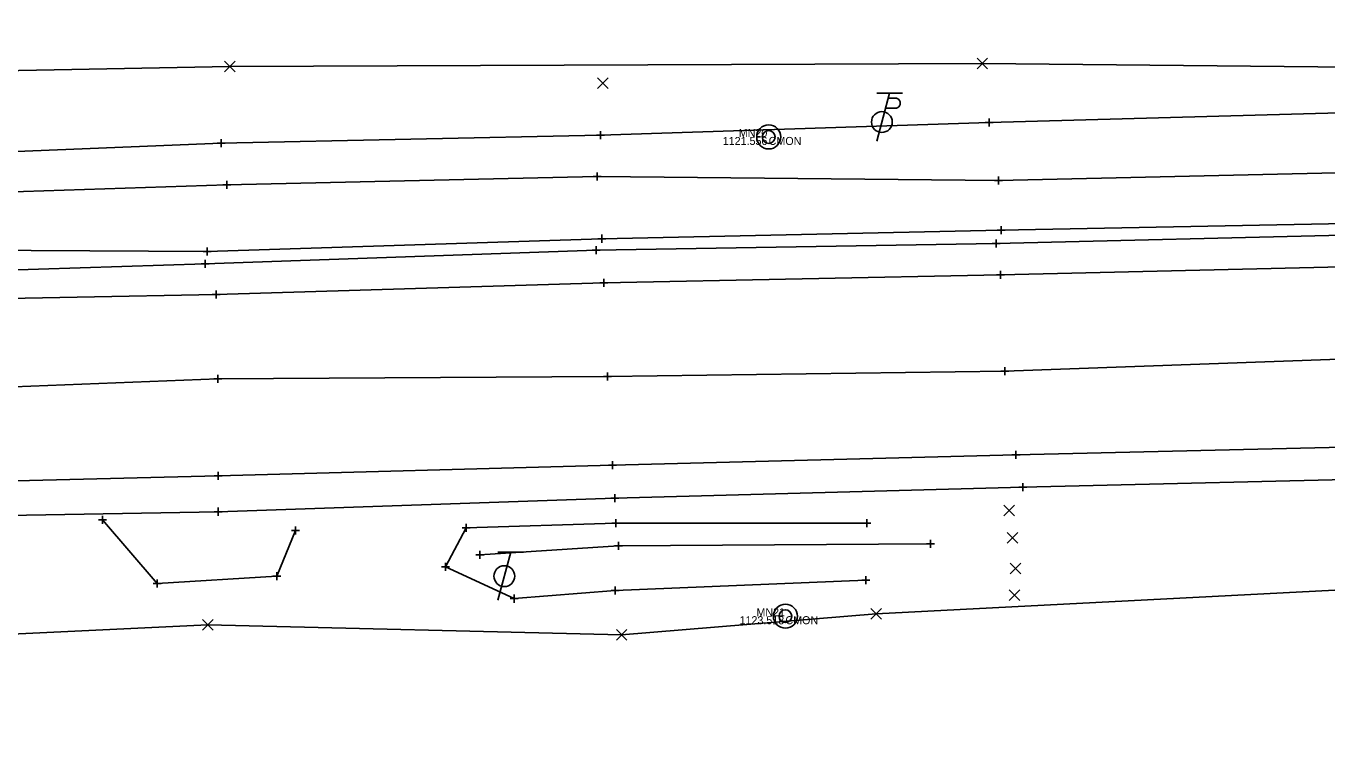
# Model space of a CAD drawing. Extents: x 2402028 to 2407435, y 498611 to 499105.
# Drawn here: x 2403515.5 to 2403678, y 498636.3 to 498725.5 of the extents above; entities that cross this region are included whole.
import ezdxf

# ---------------------------------------------------------------- set-up
doc = ezdxf.new("R2010")
doc.units = 0
for name, color, linetype in [('_CIVIL_CONSTRUCTION', 7, 'Continuous'), ('DR_X_Ditch', 7, 'Continuous'), ('PV_X_COP', 7, 'Continuous'), ('PV_X_Driveway', 7, 'Continuous'), ('PV_X_EOP', 7, 'Continuous'), ('PV_X_Shoulder', 7, 'Continuous'), ('RW_X_CL_1000_Distances', 7, 'Continuous'), ('RW_X_CL_100_Bearings', 7, 'Continuous'), ('RW_X_CL_100_Cardinal_Points', 7, 'Continuous'), ('RW_X_CL_100_Stations', 7, 'Continuous'), ('RW_X_CL_500_Bearings', 7, 'Continuous'), ('RW_X_CL_500_Cardinal_Points', 7, 'Continuous'), ('RW_X_CL_500_Stations', 7, 'Continuous'), ('SV_X_Break_Lines', 7, 'Continuous'), ('SV_X_Terrain_Boundary', 7, 'Continuous')]:
    doc.layers.add(name, color=color, linetype=linetype)

msp = doc.modelspace()

# ---------------------------------------------------------------- linework, layer by layer
at = {"layer": 'DR_X_Ditch'}
for points in [[(2403115.12, 498695.09), (2403139.28, 498697.03), (2403188.69, 498698.47), (2403237.26, 498698.52), (2403287.58, 498700.04), (2403338.31, 498701.02), (2403388.05, 498703.88), (2403439.2, 498702.19), (2403487.16, 498703.92), (2403540.55, 498705.7), (2403586.78, 498706.71), (2403636.91, 498706.23), (2403686.46, 498707.34), (2403736.22, 498708.05), (2403785.8, 498709.01), (2403836.25, 498710.7), (2403885.81, 498712.33), (2403935.71, 498713.55), (2403984.74, 498715.92), (2404035.79, 498716.24), (2404057.73, 498716.67)], [(2403628.45, 498660.85), (2403589.45, 498660.61), (2403572.15, 498659.5)]]:
    msp.add_lwpolyline(points, dxfattribs=at)
at = {"layer": 'PV_X_COP'}
msp.add_lwpolyline([(2403339.4, 498675.07), (2403388.6, 498676.54), (2403439.52, 498678.71), (2403488.39, 498679.45), (2403539.43, 498681.45), (2403588.1, 498681.77), (2403637.7, 498682.43), (2403687.6, 498684.21), (2403737.23, 498685.84), (2403787.81, 498686.93), (2403836.99, 498688.45), (2403886.41, 498689.66), (2403936.62, 498690.72), (2403985.57, 498692.23), (2404036.54, 498693.02)], dxfattribs=at)
at = {"layer": 'PV_X_Driveway'}
msp.add_lwpolyline([(2403549.12, 498662.52), (2403546.79, 498656.83), (2403531.83, 498655.92), (2403525, 498663.87)], dxfattribs=at)
at = {"layer": 'PV_X_EOP'}
for points in [[(2403338.61, 498686.54), (2403387.34, 498688.53), (2403437.74, 498689.31), (2403487.06, 498690.99), (2403539.21, 498692.01), (2403587.62, 498693.45), (2403637.16, 498694.45), (2403686.98, 498695.6), (2403736.54, 498696.76), (2403786.79, 498698.23), (2403836.48, 498699.49), (2403886.02, 498700.75), (2403935.9, 498702.14), (2403985.32, 498703.46), (2404035.9, 498704.57), (2404085.81, 498705.89), (2404135.13, 498707.56), (2404185.41, 498708.59), (2404200.68, 498708.71)], [(2403340.13, 498663.91), (2403389.07, 498665.43), (2403439.65, 498666.68), (2403488.91, 498668.12), (2403539.47, 498669.35), (2403588.7, 498670.69), (2403639.11, 498671.99), (2403688.87, 498673.13), (2403737.83, 498674.5), (2403788.35, 498675.39), (2403837.8, 498676.88), (2403887.26, 498678.35), (2403937.03, 498679.79), (2403985.56, 498681.24), (2404036.04, 498682.2)]]:
    msp.add_lwpolyline(points, dxfattribs=at)
at = {"layer": 'PV_X_Shoulder'}
for p, q in [((2403586.67, 498697.53), (2403636.62, 498698.35)), ((2403636.62, 498698.35), (2403686.65, 498699.57)), ((2403537.85, 498695.8), (2403586.67, 498697.53)), ((2403487.58, 498694.22), (2403537.85, 498695.8))]:
    msp.add_line(p, q, dxfattribs=at)
msp.add_lwpolyline([(2403340.12, 498659.5), (2403389.1, 498660.69), (2403439.66, 498662.88), (2403489.16, 498663.97), (2403539.46, 498664.88), (2403589, 498666.58), (2403639.97, 498667.94), (2403689.14, 498669.11), (2403738.07, 498670.06), (2403789, 498671.54), (2403838.97, 498672.86), (2403888.69, 498674.59), (2403938.01, 498673.12), (2403986.56, 498676.91), (2404036.95, 498678.51)], dxfattribs=at)
at = {"layer": 'RW_X_CL_1000_Distances'}
for p, q in [((2403577.6, 498659.83), (2403574.4, 498659.83)), ((2403576, 498659.83), (2403574.4, 498653.83))]:
    msp.add_line(p, q, dxfattribs=at)
msp.add_circle((2403575.2, 498656.83), 1.3, dxfattribs=at)
at = {"layer": 'RW_X_CL_100_Stations'}
for centre, radius in [((2403608.22, 498711.66), 1.5), ((2403608.22, 498711.66), 0.8), ((2403610.31, 498651.83), 1.5), ((2403610.31, 498651.83), 0.8)]:
    msp.add_circle(centre, radius, dxfattribs=at)
at = {"layer": 'RW_X_CL_500_Bearings'}
for p, q in [((2403635.25, 498713.46), (2403636.25, 498713.46)), ((2403635.75, 498713.96), (2403635.75, 498712.96)), ((2403635.75, 498713.46), (2403635.75, 498713.46)), ((2403539.84, 498711.4), (2403539.84, 498710.4)), ((2403586.71, 498711.88), (2403587.71, 498711.88)), ((2403587.21, 498712.38), (2403587.21, 498711.38)), ((2403587.21, 498711.88), (2403587.21, 498711.88)), ((2403539.34, 498710.9), (2403540.34, 498710.9)), ((2403539.84, 498710.9), (2403539.84, 498710.9)), ((2403540.55, 498706.2), (2403540.55, 498705.2)), ((2403586.28, 498706.71), (2403587.28, 498706.71)), ((2403586.78, 498707.21), (2403586.78, 498706.21)), ((2403586.78, 498706.71), (2403586.78, 498706.71)), ((2403636.41, 498706.23), (2403637.41, 498706.23)), ((2403636.91, 498706.73), (2403636.91, 498705.73)), ((2403636.91, 498706.23), (2403636.91, 498706.23)), ((2403540.05, 498705.7), (2403541.05, 498705.7)), ((2403540.55, 498705.7), (2403540.55, 498705.7)), ((2403636.76, 498700.04), (2403637.76, 498700.04)), ((2403637.26, 498700.54), (2403637.26, 498699.54)), ((2403637.26, 498700.04), (2403637.26, 498700.04)), ((2403586.67, 498698.03), (2403586.67, 498697.03)), ((2403586.88, 498698.96), (2403587.88, 498698.96)), ((2403587.38, 498699.46), (2403587.38, 498698.46)), ((2403587.38, 498698.96), (2403587.38, 498698.96)), ((2403636.12, 498698.35), (2403637.12, 498698.35)), ((2403636.62, 498698.85), (2403636.62, 498697.85)), ((2403636.62, 498698.35), (2403636.62, 498698.35)), ((2403537.59, 498697.36), (2403538.59, 498697.36)), ((2403538.09, 498697.86), (2403538.09, 498696.86)), ((2403538.09, 498697.36), (2403538.09, 498697.36)), ((2403586.17, 498697.53), (2403587.17, 498697.53)), ((2403586.67, 498697.53), (2403586.67, 498697.53)), ((2403537.35, 498695.8), (2403538.35, 498695.8)), ((2403537.85, 498696.3), (2403537.85, 498695.3)), ((2403537.85, 498695.8), (2403537.85, 498695.8)), ((2403637.16, 498694.95), (2403637.16, 498693.95)), ((2403587.12, 498693.45), (2403588.12, 498693.45)), ((2403587.62, 498693.95), (2403587.62, 498692.95)), ((2403587.62, 498693.45), (2403587.62, 498693.45)), ((2403636.66, 498694.45), (2403637.66, 498694.45)), ((2403637.16, 498694.45), (2403637.16, 498694.45)), ((2403538.71, 498692.01), (2403539.71, 498692.01)), ((2403539.21, 498692.51), (2403539.21, 498691.51)), ((2403539.21, 498692.01), (2403539.21, 498692.01)), ((2403539.43, 498681.95), (2403539.43, 498680.95)), ((2403587.6, 498681.77), (2403588.6, 498681.77)), ((2403588.1, 498682.27), (2403588.1, 498681.27)), ((2403588.1, 498681.77), (2403588.1, 498681.77)), ((2403637.2, 498682.43), (2403638.2, 498682.43)), ((2403637.7, 498682.93), (2403637.7, 498681.93)), ((2403637.7, 498682.43), (2403637.7, 498682.43)), ((2403538.93, 498681.45), (2403539.93, 498681.45)), ((2403539.43, 498681.45), (2403539.43, 498681.45)), ((2403639.11, 498672.49), (2403639.11, 498671.49)), ((2403588.2, 498670.69), (2403589.2, 498670.69)), ((2403588.7, 498671.19), (2403588.7, 498670.19)), ((2403588.7, 498670.69), (2403588.7, 498670.69)), ((2403638.61, 498671.99), (2403639.61, 498671.99)), ((2403639.11, 498671.99), (2403639.11, 498671.99)), ((2403538.97, 498669.35), (2403539.97, 498669.35)), ((2403539.47, 498669.85), (2403539.47, 498668.85)), ((2403539.47, 498669.35), (2403539.47, 498669.35)), ((2403639.47, 498667.94), (2403640.47, 498667.94)), ((2403639.97, 498668.44), (2403639.97, 498667.44)), ((2403639.97, 498667.94), (2403639.97, 498667.94)), ((2403588.5, 498666.58), (2403589.5, 498666.58)), ((2403589, 498667.08), (2403589, 498666.08)), ((2403589, 498666.58), (2403589, 498666.58)), ((2403525, 498664.37), (2403525, 498663.37)), ((2403538.96, 498664.88), (2403539.96, 498664.88)), ((2403539.46, 498665.38), (2403539.46, 498664.38)), ((2403539.46, 498664.88), (2403539.46, 498664.88)), ((2403589.11, 498663.93), (2403589.11, 498662.93)), ((2403620.48, 498663.96), (2403620.48, 498662.96)), ((2403524.5, 498663.87), (2403525.5, 498663.87)), ((2403525, 498663.87), (2403525, 498663.87)), ((2403548.62, 498662.52), (2403549.62, 498662.52)), ((2403549.12, 498663.02), (2403549.12, 498662.02)), ((2403549.12, 498662.52), (2403549.12, 498662.52)), ((2403569.92, 498662.85), (2403570.92, 498662.85)), ((2403570.42, 498663.35), (2403570.42, 498662.35)), ((2403570.42, 498662.85), (2403570.42, 498662.85)), ((2403588.61, 498663.43), (2403589.61, 498663.43)), ((2403589.11, 498663.43), (2403589.11, 498663.43)), ((2403619.98, 498663.46), (2403620.98, 498663.46)), ((2403620.48, 498663.46), (2403620.48, 498663.46)), ((2403589.45, 498661.11), (2403589.45, 498660.11)), ((2403627.95, 498660.85), (2403628.95, 498660.85)), ((2403628.45, 498661.35), (2403628.45, 498660.35)), ((2403628.45, 498660.85), (2403628.45, 498660.85)), ((2403571.65, 498659.5), (2403572.65, 498659.5)), ((2403572.15, 498660), (2403572.15, 498659)), ((2403572.15, 498659.5), (2403572.15, 498659.5)), ((2403588.95, 498660.61), (2403589.95, 498660.61)), ((2403589.45, 498660.61), (2403589.45, 498660.61)), ((2403567.33, 498658.01), (2403568.33, 498658.01)), ((2403567.83, 498658.51), (2403567.83, 498657.51)), ((2403567.83, 498658.01), (2403567.83, 498658.01)), ((2403531.33, 498655.92), (2403532.33, 498655.92)), ((2403531.83, 498656.42), (2403531.83, 498655.42)), ((2403531.83, 498655.92), (2403531.83, 498655.92)), ((2403546.29, 498656.83), (2403547.29, 498656.83)), ((2403546.79, 498657.33), (2403546.79, 498656.33)), ((2403546.79, 498656.83), (2403546.79, 498656.83)), ((2403619.87, 498656.34), (2403620.87, 498656.34)), ((2403620.37, 498656.84), (2403620.37, 498655.84)), ((2403620.37, 498656.34), (2403620.37, 498656.34)), ((2403576.41, 498654.52), (2403576.41, 498653.52)), ((2403588.56, 498655.02), (2403589.56, 498655.02)), ((2403589.06, 498655.52), (2403589.06, 498654.52)), ((2403589.06, 498655.02), (2403589.06, 498655.02)), ((2403575.91, 498654.02), (2403576.91, 498654.02)), ((2403576.41, 498654.02), (2403576.41, 498654.02))]:
    msp.add_line(p, q, dxfattribs=at)
at = {"layer": 'RW_X_CL_500_Cardinal_Points'}
for p, q in [((2403624.92, 498717.12), (2403621.72, 498717.12)), ((2403623.32, 498717.12), (2403621.72, 498711.12)), ((2403623.16, 498716.52), (2403624.01, 498716.52)), ((2403622.82, 498715.24), (2403624.01, 498715.24))]:
    msp.add_line(p, q, dxfattribs=at)
msp.add_circle((2403622.36, 498713.52), 1.3, dxfattribs=at)
msp.add_arc((2403624.02, 498715.88), 0.638, 268.8767, 91.1233, dxfattribs=at)
at = {"layer": 'RW_X_CL_500_Stations'}
for p, q in [((2403540.24, 498719.8), (2403541.57, 498721.13)), ((2403540.24, 498721.13), (2403541.57, 498719.8)), ((2403634.24, 498720.16), (2403635.57, 498721.49)), ((2403634.24, 498721.49), (2403635.57, 498720.16)), ((2403586.82, 498717.71), (2403588.15, 498719.05)), ((2403586.82, 498719.05), (2403588.15, 498717.71)), ((2403637.61, 498664.37), (2403638.94, 498665.71)), ((2403637.61, 498665.71), (2403638.94, 498664.37)), ((2403638.02, 498660.94), (2403639.35, 498662.28)), ((2403638.02, 498662.28), (2403639.35, 498660.94)), ((2403638.38, 498657.11), (2403639.72, 498658.44)), ((2403638.38, 498658.44), (2403639.72, 498657.11)), ((2403638.24, 498653.78), (2403639.57, 498655.11)), ((2403638.24, 498655.11), (2403639.57, 498653.78)), ((2403620.99, 498651.46), (2403622.32, 498652.8)), ((2403620.99, 498652.8), (2403622.32, 498651.46)), ((2403537.51, 498650.08), (2403538.85, 498651.41)), ((2403537.51, 498651.41), (2403538.85, 498650.08)), ((2403589.19, 498648.85), (2403590.52, 498650.19)), ((2403589.19, 498650.19), (2403590.52, 498648.85))]:
    msp.add_line(p, q, dxfattribs=at)
at = {"layer": 'SV_X_Break_Lines'}
for points in [[(2404019.04, 498713.49), (2404033.84, 498711.06), (2404059.48, 498713.51), (2404061.23, 498716.75), (2404058.41, 498720.02), (2404035.5, 498720.85), (2403984.19, 498717.86), (2403935.32, 498717.7), (2403885.41, 498717.04), (2403835.4, 498717.35), (2403785.05, 498718.48), (2403735.06, 498717.48), (2403685.61, 498714.83), (2403635.75, 498713.46), (2403587.21, 498711.88)], [(2403337.63, 498692.95), (2403385.67, 498694.88), (2403436.95, 498695.07), (2403486.78, 498697.64), (2403538.09, 498697.36), (2403587.38, 498698.96), (2403637.26, 498700.04), (2403686.76, 498700.96), (2403736.62, 498703.7), (2403786.43, 498704.02), (2403835.95, 498705.28), (2403885.12, 498707.9), (2403935.66, 498709.22), (2403986.83, 498710.71), (2404005.79, 498712.51)], [(2403587.21, 498711.88), (2403539.84, 498710.9), (2403487.68, 498708.78), (2403439.88, 498710.16), (2403387.81, 498709.86), (2403338.45, 498707.66)], [(2403620.48, 498663.46), (2403589.11, 498663.43), (2403570.42, 498662.85), (2403567.83, 498658.01), (2403576.41, 498654.02), (2403589.06, 498655.02), (2403620.37, 498656.34)]]:
    msp.add_lwpolyline(points, dxfattribs=at)
at = {"layer": 'SV_X_Terrain_Boundary'}
for points in [[(2404013.92, 498724.8), (2403983.78, 498725.5), (2403934.83, 498724.06), (2403835.07, 498723.66), (2403784.93, 498723.31), (2403734.98, 498722.37), (2403685.18, 498720.34), (2403634.9, 498720.82), (2403540.9, 498720.47), (2403442.1, 498718.56), (2403390.54, 498717.85), (2403340.67, 498716.01)], [(2403346.11, 498636.26), (2403438.36, 498646.02), (2403538.18, 498650.74), (2403589.85, 498649.52), (2403621.66, 498652.13), (2403687.01, 498655.49), (2403736.24, 498654.29), (2403786.5, 498662.01), (2403837.7, 498657.06), (2403883.46, 498651.52), (2403933.92, 498653.73), (2403937.33, 498653.02), (2403944.86, 498652.27), (2403985.55, 498656.18), (2404071.93, 498644.97)]]:
    msp.add_lwpolyline(points, dxfattribs=at)

# ---------------------------------------------------------------- texts
at = {"layer": '_CIVIL_CONSTRUCTION'}
for s, p in [('MN20', (2403604.48, 498711.66)), ('MN21', (2403606.69, 498651.83))]:
    msp.add_text(s, height=1, dxfattribs=at).set_placement(p)
at = {"layer": 'RW_X_CL_100_Bearings'}
for s, p in [('1121.556', (2403602.48, 498710.66)), ('1123.518', (2403604.58, 498650.83))]:
    msp.add_text(s, height=1, dxfattribs=at).set_placement(p)
at = {"layer": 'RW_X_CL_100_Cardinal_Points'}
for p in [(2403608.22, 498710.66), (2403610.31, 498650.83)]:
    msp.add_text('CMON', height=1, dxfattribs=at).set_placement(p)

doc.saveas('drawing.dxf')
